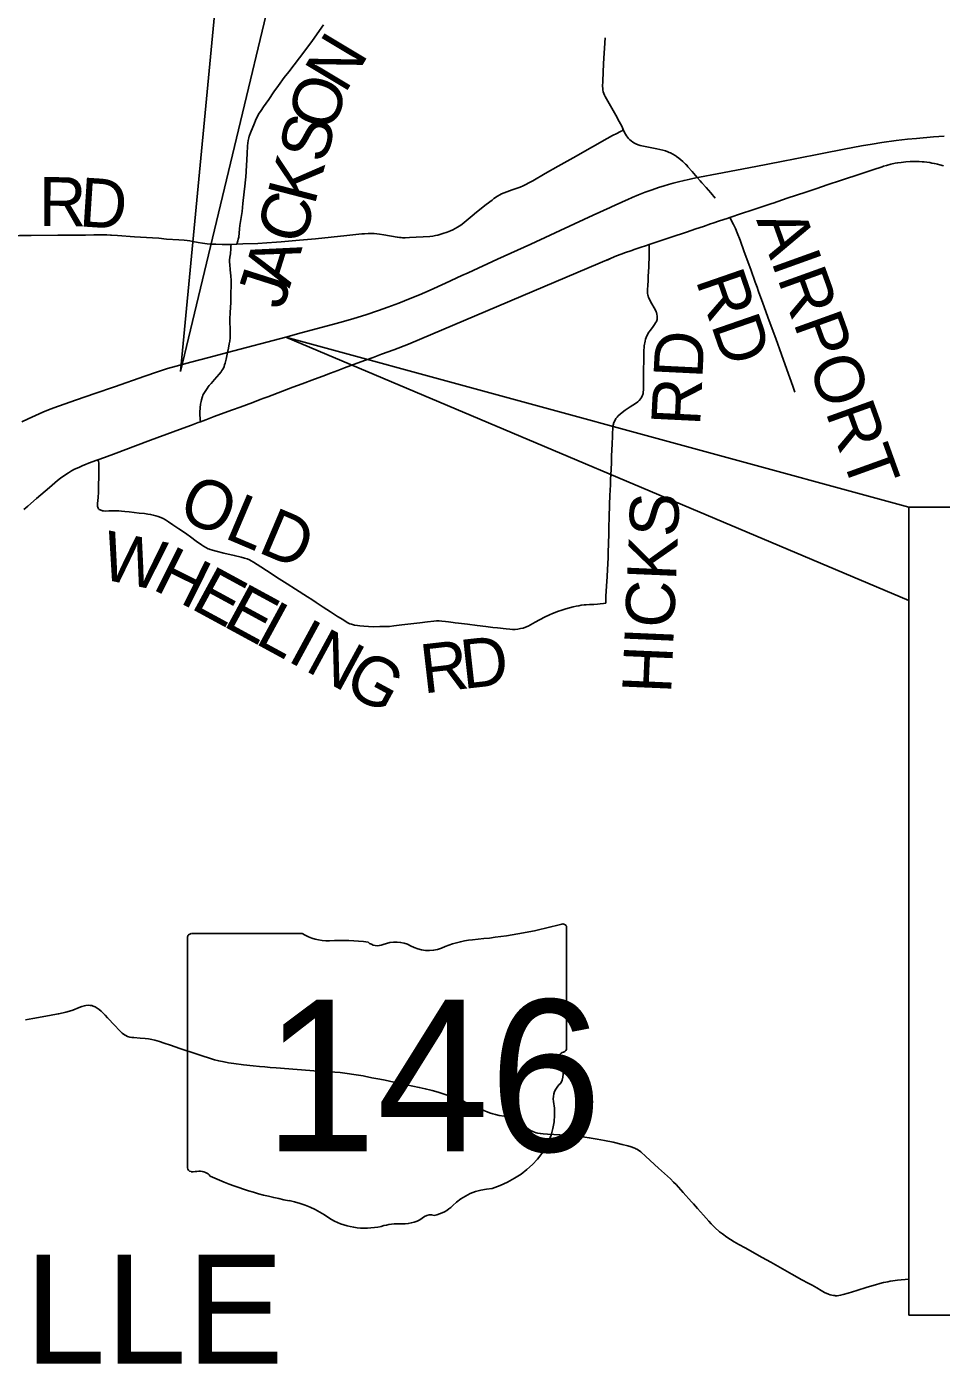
# Model space of a CAD drawing. Extents: x 1761803 to 2441803, y 509895 to 949895.
# Drawn here: x 2124353 to 2141149, y 790412 to 814988 of the extents above; entities that cross this region are included whole.
import ezdxf

# ---------------------------------------------------------------- set-up
doc = ezdxf.new("R2010")
doc.units = 0
for name, color, linetype in [('GM_X_County_Road', 7, 'Continuous'), ('GM_X_Minor_Lake', 7, 'Continuous'), ('GM_X_Minor_River', 7, 'Continuous'), ('GM_X_Minor_River_Text', 7, 'Continuous'), ('GM_X_State_Location', 7, 'Continuous'), ('GM_X_Township_Road', 7, 'Continuous')]:
    doc.layers.add(name, color=color, linetype=linetype)

msp = doc.modelspace()

# ---------------------------------------------------------------- linework, layer by layer
at = {"layer": 'GM_X_County_Road'}
for points in [[(2129165, 814161), (2129458, 814549), (2129600, 814737), (2129806, 815021)], [(2135308, 813102), (2135280, 813161), (2135235, 813247), (2135172, 813364), (2134976, 813705), (2134962, 813735), (2134951, 813765), (2134942, 813796), (2134935, 813828), (2134931, 813860), (2134930, 813892), (2134932, 813990), (2134948, 814312), (2134974, 814787)], [(2128212, 810995), (2128231, 811058), (2128237, 811085), (2128246, 811125), (2128259, 811278), (2128267, 811338), (2128307, 811596), (2128324, 811745), (2128367, 812116), (2128373, 812181), (2128377, 812229), (2128399, 812654), (2128407, 812801), (2128412, 812850), (2128420, 812898), (2128431, 812946), (2128441, 812977), (2128446, 812992), (2128463, 813038), (2128475, 813068), (2128524, 813190), (2128568, 813295), (2128589, 813340), (2128612, 813383), (2128656, 813452), (2128702, 813520), (2128797, 813653), (2128892, 813792), (2128977, 813911), (2129081, 814055), (2129165, 814161)], [(2132900, 811807), (2132934, 811833), (2132999, 811880), (2133039, 811905), (2133073, 811922), (2133119, 811941), (2133269, 811994), (2133414, 812045), (2133473, 812068), (2133517, 812090), (2133574, 812121), (2133645, 812161), (2133872, 812292), (2134116, 812427), (2134387, 812580), (2134743, 812782), (2135014, 812935), (2135114, 812989), (2135188, 813029), (2135247, 813057), (2135270, 813068), (2135286, 813080), (2135308, 813102)], [(2136151, 812681), (2136129, 812690), (2136083, 812707), (2136035, 812721), (2135923, 812746), (2135650, 812801), (2135618, 812809), (2135584, 812820), (2135539, 812839), (2135513, 812852), (2135485, 812870), (2135455, 812893), (2135432, 812913), (2135408, 812936), (2135387, 812961), (2135369, 812987), (2135351, 813016), (2135333, 813047), (2135308, 813102)], [(2136280, 812612), (2136261, 812624), (2136218, 812648), (2136174, 812671), (2136151, 812681)], [(2136474, 812444), (2136452, 812467), (2136405, 812513), (2136368, 812546), (2136329, 812577), (2136289, 812606), (2136280, 812612)], [(2136994, 811840), (2136916, 811936), (2136829, 812034), (2136749, 812125), (2136721, 812157), (2136668, 812219), (2136572, 812332), (2136497, 812419), (2136474, 812444)], [(2132380, 811386), (2132384, 811388), (2132388, 811391), (2132535, 811518), (2132611, 811581), (2132792, 811722), (2132900, 811807)], [(2128212, 810995), (2128321, 811000), (2128599, 811011), (2128763, 811020), (2128940, 811030), (2129024, 811037), (2129365, 811070), (2129659, 811095), (2130229, 811156), (2130506, 811184), (2130555, 811188), (2130621, 811191), (2130686, 811191), (2130735, 811189), (2130784, 811185), (2130833, 811179), (2130914, 811167), (2131158, 811127), (2131202, 811119), (2131227, 811117), (2131253, 811115), (2131302, 811114), (2131383, 811117), (2131759, 811140), (2131810, 811145), (2131858, 811154), (2131903, 811164), (2131997, 811192), (2132074, 811218), (2132135, 811241), (2132180, 811261), (2132224, 811282), (2132266, 811307), (2132323, 811344), (2132380, 811386)], [(2137767, 810205), (2137733, 810298), (2137649, 810529), (2137532, 810853), (2137453, 811068), (2137400, 811206), (2137369, 811282), (2137334, 811356), (2137269, 811488)], [(2123340, 810199), (2123493, 810385), (2123751, 810703), (2124047, 811054), (2124099, 811111), (2124113, 811122), (2124127, 811131), (2124143, 811138), (2124158, 811143), (2124173, 811147), (2124189, 811150), (2124221, 811153), (2124270, 811156), (2124434, 811156), (2124926, 811161), (2125171, 811164), (2125433, 811164), (2125586, 811166)], [(2125586, 811166), (2125630, 811166), (2125712, 811167), (2125826, 811165), (2125894, 811162)], [(2125894, 811162), (2125908, 811161), (2126022, 811154), (2126333, 811132), (2126660, 811111), (2126780, 811104), (2126921, 811091), (2127149, 811073), (2127247, 811067), (2127297, 811063), (2127351, 811056), (2127406, 811046), (2127502, 811028), (2127583, 811014), (2127664, 811004), (2127746, 810997), (2127828, 810994), (2127943, 810992), (2128105, 810991)], [(2127544, 807736), (2127540, 807773), (2127537, 807803), (2127532, 807855), (2127535, 807910), (2127540, 807989), (2127547, 808060), (2127555, 808106), (2127562, 808138), (2127572, 808178), (2127579, 808199), (2127589, 808226), (2127605, 808253), (2127628, 808289), (2127665, 808347), (2127686, 808378), (2127705, 808403), (2127738, 808440), (2127770, 808477), (2127804, 808514), (2127847, 808561), (2127890, 808611), (2127921, 808650), (2127939, 808677), (2127956, 808704), (2127970, 808730), (2127978, 808749), (2127988, 808780), (2127996, 808812), (2128013, 808887), (2128040, 809008), (2128057, 809084), (2128073, 809165), (2128081, 809214), (2128089, 809279), (2128092, 809361), (2128092, 809411), (2128086, 809592), (2128086, 809657), (2128088, 809706), (2128091, 809756), (2128093, 809822), (2128100, 809936), (2128102, 810055), (2128108, 810273), (2128107, 810331), (2128101, 810413), (2128091, 810527), (2128080, 810621), (2128077, 810665), (2128079, 810705), (2128085, 810756), (2128094, 810819), (2128103, 810915), (2128104, 810955), (2128105, 810991)], [(2128105, 810991), (2128212, 810995)], [(2134989, 804406), (2134989, 804459), (2134991, 804533), (2135002, 804718), (2135012, 804892), (2135020, 805023), (2135029, 805236), (2135034, 805384), (2135036, 805449), (2135039, 805548), (2135041, 805630), (2135042, 805695), (2135044, 805760), (2135046, 805842), (2135048, 805940), (2135052, 806054), (2135056, 806136), (2135058, 806218), (2135065, 806381), (2135068, 806480), (2135072, 806578), (2135075, 806676), (2135084, 806856), (2135090, 806987), (2135095, 807102), (2135106, 807331), (2135111, 807463), (2135114, 807544), (2135116, 807593), (2135120, 807642), (2135124, 807674), (2135128, 807690), (2135132, 807706), (2135143, 807736), (2135158, 807766), (2135175, 807793), (2135195, 807818), (2135217, 807842), (2135253, 807876), (2135291, 807906), (2135343, 807946), (2135383, 807974), (2135438, 808010), (2135534, 808073), (2135574, 808102), (2135595, 808120), (2135602, 808127), (2135631, 808163), (2135640, 808177), (2135648, 808191), (2135662, 808221), (2135667, 808237), (2135672, 808253), (2135677, 808285), (2135681, 808318), (2135683, 808367), (2135683, 808482), (2135683, 808564), (2135682, 808679), (2135685, 808875), (2135687, 808973), (2135687, 809022), (2135688, 809055), (2135690, 809095), (2135693, 809127), (2135698, 809157), (2135704, 809185), (2135709, 809216), (2135718, 809252), (2135729, 809284), (2135748, 809325), (2135778, 809378), (2135806, 809418), (2135856, 809482), (2135885, 809521), (2135903, 809549), (2135918, 809578), (2135924, 809594), (2135929, 809610), (2135932, 809626), (2135933, 809642), (2135934, 809659), (2135933, 809676), (2135927, 809708), (2135919, 809740), (2135913, 809756), (2135899, 809786), (2135876, 809829), (2135835, 809901), (2135811, 809943), (2135788, 809986), (2135775, 810016), (2135764, 810047), (2135761, 810062), (2135756, 810094), (2135755, 810127), (2135756, 810159), (2135761, 810241), (2135765, 810322), (2135769, 810403), (2135777, 810583), (2135784, 810794), (2135786, 810875), (2135787, 810990)], [(2137789, 810145), (2137767, 810205)], [(2138459, 808279), (2138424, 808386), (2138370, 808541), (2138313, 808695), (2138214, 808973), (2138108, 809266), (2137990, 809589), (2137873, 809913), (2137795, 810129), (2137789, 810145)], [(2125660, 807038), (2125670, 807007), (2125675, 806982), (2125678, 806936), (2125680, 806867), (2125679, 806737), (2125673, 806558), (2125671, 806509), (2125668, 806443), (2125662, 806346), (2125652, 806232), (2125651, 806199), (2125652, 806182), (2125656, 806166), (2125663, 806150), (2125673, 806137), (2125686, 806126), (2125700, 806117), (2125715, 806109), (2125731, 806104), (2125747, 806101), (2125764, 806099), (2125796, 806096), (2125862, 806097), (2125977, 806099), (2126042, 806099), (2126091, 806096), (2126156, 806089), (2126237, 806080), (2126416, 806060), (2126513, 806049), (2126578, 806041), (2126627, 806033), (2126675, 806022), (2126722, 806010), (2126769, 805995), (2126814, 805977), (2126858, 805956), (2126901, 805933), (2126957, 805899), (2127038, 805844), (2127147, 805771), (2127158, 805764)], [(2127158, 805764), (2127295, 805669), (2127362, 805621), (2127467, 805544), (2127561, 805478), (2127602, 805450), (2127644, 805425), (2127688, 805403), (2127711, 805394)], [(2127711, 805394), (2127719, 805391), (2127766, 805376), (2127829, 805359), (2127973, 805324), (2128165, 805280), (2128292, 805250), (2128355, 805233), (2128402, 805217), (2128447, 805199), (2128476, 805184), (2128518, 805159), (2128655, 805069), (2128861, 804935), (2128943, 804880), (2129039, 804818), (2129133, 804758), (2129287, 804662), (2129510, 804520), (2129590, 804470), (2129669, 804417), (2129797, 804333), (2129934, 804243), (2130062, 804162), (2130156, 804105), (2130240, 804052), (2130290, 804027), (2130317, 804018), (2130333, 804013)], [(2132099, 804060), (2132187, 804050), (2132219, 804046), (2132284, 804038), (2132446, 804018), (2132624, 803995), (2132786, 803975), (2132916, 803960), (2132997, 803951), (2133160, 803931), (2133225, 803924), (2133274, 803922), (2133324, 803923), (2133373, 803928), (2133421, 803937), (2133469, 803948), (2133516, 803964), (2133561, 803982), (2133605, 804004), (2133691, 804053), (2133864, 804145), (2133952, 804190), (2134011, 804217), (2134056, 804236), (2134103, 804252), (2134180, 804277), (2134257, 804302), (2134321, 804321), (2134391, 804339), (2134445, 804351), (2134491, 804358), (2134538, 804365), (2134593, 804373), (2134626, 804376), (2134690, 804379), (2134770, 804383), (2134835, 804387), (2134884, 804392), (2134947, 804399), (2134989, 804406)], [(2130333, 804013), (2130372, 804003), (2130425, 803995), (2130471, 803988), (2130544, 803980), (2130632, 803974), (2130719, 803971), (2130836, 803973), (2130934, 803974), (2131016, 803978), (2131098, 803986), (2131244, 804004), (2131570, 804041), (2131716, 804060), (2131830, 804073), (2131879, 804077), (2131927, 804077), (2131976, 804074), (2132041, 804068), (2132099, 804060), (2132099, 804060)]]:
    msp.add_lwpolyline(points, dxfattribs=at)
at = {"layer": 'GM_X_Minor_Lake'}
for points in [[(2124933, 796865), (2124941, 796867), (2125073, 796893), (2125138, 796912), (2125199, 796933), (2125316, 796980), (2125365, 797000), (2125412, 797013), (2125440, 797019), (2125481, 797022), (2125518, 797020), (2125546, 797015), (2125573, 797006), (2125610, 796990), (2125647, 796969), (2125682, 796945), (2125720, 796910), (2125768, 796865), (2125792, 796838), (2125836, 796789), (2125970, 796648), (2126053, 796562), (2126105, 796512), (2126132, 796491), (2126158, 796472), (2126172, 796464), (2126203, 796449), (2126244, 796437), (2126281, 796432), (2126320, 796428), (2126434, 796419), (2126527, 796412), (2126592, 796402), (2126650, 796391), (2126708, 796378), (2126789, 796357), (2126874, 796328), (2126994, 796287)], [(2124332, 796752), (2124462, 796776), (2124768, 796832), (2124933, 796865)], [(2126994, 796287), (2127163, 796228), (2127802, 796021), (2127881, 796001), (2127977, 795980), (2128058, 795966), (2128155, 795952), (2128334, 795929), (2128513, 795909), (2128627, 795897), (2128725, 795889), (2128822, 795881), (2128936, 795874), (2129703, 795814), (2130014, 795792), (2130112, 795784), (2130193, 795774), (2130404, 795744), (2130534, 795725), (2130557, 795720), (2130694, 795691), (2130839, 795663), (2130935, 795643), (2131095, 795609), (2131561, 795512), (2131673, 795488), (2131773, 795462)], [(2131773, 795462), (2131800, 795455), (2131911, 795423), (2132036, 795384), (2132160, 795342), (2132252, 795307), (2132385, 795253), (2132404, 795245), (2132539, 795186), (2132748, 795091), (2132809, 795065), (2132854, 795047), (2132916, 795027), (2132963, 795013), (2133027, 794999), (2133123, 794982), (2133196, 794973), (2133247, 794963), (2133284, 794951), (2133318, 794938), (2133348, 794921), (2133375, 794906), (2133413, 794877), (2133464, 794835), (2133539, 794771), (2133564, 794751), (2133604, 794724), (2133647, 794701), (2133677, 794689), (2133708, 794680), (2133739, 794672), (2133787, 794664), (2133836, 794659), (2133918, 794655), (2134032, 794650), (2134262, 794639), (2134360, 794631), (2134386, 794628), (2134441, 794621), (2134684, 794588), (2134830, 794563), (2134962, 794541), (2135121, 794506), (2135286, 794464), (2135391, 794439), (2135454, 794421), (2135501, 794406), (2135532, 794394), (2135542, 794388), (2135561, 794378), (2135588, 794359), (2135631, 794328), (2135723, 794245), (2135956, 794031), (2136064, 793932), (2136174, 793832), (2136232, 793775), (2136278, 793728), (2136410, 793584), (2136562, 793412), (2136596, 793376), (2136673, 793291), (2136782, 793169), (2136880, 793059), (2136925, 793011), (2136993, 792940), (2137078, 792864), (2137130, 792824), (2137209, 792766), (2137277, 792721), (2137347, 792679), (2137433, 792630), (2137547, 792566), (2137862, 792391), (2138019, 792302), (2138405, 792086), (2138590, 791982), (2138705, 791919), (2138776, 791879), (2138861, 791830), (2138946, 791781), (2139004, 791750), (2139048, 791729), (2139067, 791721), (2139078, 791716), (2139109, 791706), (2139140, 791698), (2139172, 791692), (2139196, 791690), (2139204, 791689), (2139237, 791689), (2139269, 791692), (2139301, 791697), (2139348, 791709), (2139442, 791738), (2139598, 791787), (2139786, 791844), (2139943, 791889), (2140022, 791911), (2140086, 791928), (2140133, 791939), (2140165, 791945), (2140213, 791953), (2140261, 791961), (2140343, 791971), (2140551, 791993)]]:
    msp.add_lwpolyline(points, dxfattribs=at)
at = {"layer": 'GM_X_Minor_River'}
msp.add_lwpolyline([(2124261, 807734), (2124378, 807792), (2124513, 807853), (2124648, 807911), (2124786, 807965), (2124939, 808022), (2125265, 808135), (2125605, 808254), (2125962, 808378), (2126519, 808573), (2126752, 808651), (2126940, 808711), (2127097, 808757), (2127366, 808831), (2127699, 808918), (2128040, 809008), (2129111, 809291), (2129396, 809368), (2129967, 809519), (2130173, 809575), (2130362, 809631), (2130581, 809701), (2130814, 809779), (2130984, 809839), (2131184, 809914), (2131398, 809998), (2131565, 810067), (2131760, 810152), (2132044, 810281), (2132342, 810418), (2132346, 810420), (2132462, 810472), (2132999, 810719), (2133610, 810999), (2134414, 811370), (2134758, 811526), (2135071, 811670), (2135182, 811722), (2135205, 811732), (2135296, 811774), (2135393, 811817), (2135474, 811853), (2135591, 811902), (2135714, 811950), (2135841, 811996), (2135959, 812036), (2136061, 812067), (2136142, 812091), (2136225, 812116), (2136324, 812142), (2136425, 812166), (2136536, 812192), (2136668, 812219), (2136709, 812227), (2137036, 812289), (2137746, 812424), (2138218, 812517), (2138463, 812565), (2138962, 812662), (2139364, 812739), (2139687, 812801), (2139881, 812834), (2140059, 812862), (2140319, 812897), (2140530, 812923), (2140694, 812939), (2141004, 812964), (2141204, 812980)], dxfattribs=at)
at = {"layer": 'GM_X_Minor_River_Text'}
for points in [[(2138060, 811752), (2138149, 811782), (2138320, 811839), (2138663, 811954), (2138865, 812020), (2139052, 812083), (2139317, 812171), (2139675, 812290), (2139893, 812364), (2140064, 812419), (2140089, 812426), (2140143, 812442), (2140222, 812463), (2140302, 812481), (2140350, 812490), (2140415, 812498), (2140496, 812506), (2140578, 812511), (2140660, 812513), (2140742, 812512), (2140797, 812509), (2140838, 812505), (2140887, 812500), (2140938, 812493), (2140977, 812486), (2141019, 812479), (2141058, 812471), (2141081, 812465), (2141121, 812455), (2141193, 812435)], [(2137269, 811488), (2137355, 811518), (2137388, 811529), (2137760, 811652), (2137853, 811684), (2137980, 811725), (2138040, 811745), (2138060, 811752)], [(2135016, 810704), (2135089, 810740), (2135182, 810781), (2135268, 810814), (2135349, 810842), (2135446, 810875), (2135527, 810903), (2135638, 810940), (2135720, 810968), (2135787, 810990), (2136003, 811061), (2136189, 811124), (2136469, 811219), (2136640, 811276), (2136780, 811323), (2136909, 811367)], [(2136909, 811367), (2136951, 811381), (2137076, 811423), (2137215, 811470), (2137269, 811488)], [(2128707, 808168), (2128779, 808196), (2129240, 808368), (2129409, 808431), (2129640, 808515), (2129793, 808574), (2129931, 808625), (2130069, 808677), (2130192, 808723), (2130423, 808809), (2130576, 808867), (2130715, 808918), (2130868, 808976), (2131097, 809059), (2131363, 809159), (2135084, 810738), (2135089, 810740)], [(2124298, 806122), (2124373, 806186), (2124534, 806326), (2124769, 806530), (2124919, 806657), (2124971, 806697), (2125037, 806744), (2125120, 806798), (2125176, 806832), (2125233, 806863), (2125307, 806898), (2125382, 806931), (2125431, 806950), (2125489, 806972), (2125642, 807031), (2125660, 807038), (2125781, 807081), (2125996, 807161), (2126350, 807291), (2126626, 807395), (2127041, 807549), (2127226, 807618), (2127380, 807675), (2127503, 807720), (2127544, 807736), (2127641, 807771), (2127795, 807829), (2127979, 807898), (2128133, 807954), (2128272, 808006), (2128503, 808091), (2128641, 808143), (2128707, 808168)]]:
    msp.add_lwpolyline(points, dxfattribs=at)
at = {"layer": 'GM_X_State_Location'}
for points in [[(2127176, 808660), (2128253, 819961), (2129889, 819961)], [(2129111, 809291), (2140551, 806169), (2140551, 804452)], [(2140551, 791334), (2169928, 791334), (2169928, 806169), (2140551, 806169)]]:
    msp.add_lwpolyline(points, close=True, dxfattribs=at)
at = {"layer": 'GM_X_Township_Road'}
for p, q in [((2127308, 798265), (2127308, 794039)), ((2129415, 798338), (2127376, 798338)), ((2134269, 796232), (2134269, 798443)), ((2134268, 796232), (2134269, 796232))]:
    msp.add_line(p, q, dxfattribs=at)
for centre, major_axis, start_param, end_param in [((2131789, 804100), (7382, 0), 4.814394, 5.042369), ((2134191, 798452), (77.5, 0), 6.141152, 7.989035), ((2127387, 798274), (80.6, 0), 1.712693, 3.28349), ((2129900, 798829), (782, 0), 4.042523, 4.731795), ((2130160, 795965), (2808, 0), 1.404758, 1.657858), ((2130797, 798296), (226, 0), 3.836095, 5.185415), ((2131128, 797808), (469, 0), 0.950623, 2.079405), ((2131734, 798478), (564, 0), 4.081561, 5.145723), ((2132731, 797047), (1485, 0), 1.699011, 2.107814), ((2134251, 796070), (120, 0), 1.883978, 3.671073), ((2133488, 795790), (720, 0), 5.934695, 6.695948), ((2134186, 796223), (82.9, 0), 5.05454, 6.418171), ((2134546, 795307), (524, 0), 2.387724, 3.262537), ((2132202, 795025), (1846, 0), 5.101752, 6.440018), ((2127388, 794030), (81.4, 0), 3.00124, 4.508301), ((2127401, 794462), (621, 0), 4.665946, 4.897461), ((2127528, 793795), (224, 0), 0.519207, 1.627899), ((2130354, 797592), (5331, 0), 4.195997, 4.488961), ((2132981, 792852), (1011, 0), 1.647645, 2.488434), ((2128765, 792140), (1668, 0), 0.823519, 1.323587), ((2131700, 793629), (597, 0), 4.937069, 5.64225), ((2130569, 793774), (1058, 0), 4.026481, 4.996735), ((2131257, 793457), (564, 0), 4.691044, 5.507374), ((2131768, 793048), (159, 0), 1.147584, 2.315152), ((2131180, 792313), (870, 0), 1.495662, 1.94098)]:
    msp.add_ellipse(centre, major_axis=major_axis, ratio=0.8, start_param=start_param, end_param=end_param, dxfattribs=at)

# ---------------------------------------------------------------- texts
at = {"layer": 'GM_X_County_Road'}
for s, height, rotation, p in [('N', 900, 59.0317, (2130196, 813742)), ('O', 900, 72.8066, (2129986, 813037)), ('S', 900, 75.5962, (2129838, 812460)), ('K', 900, 75.4364, (2129638, 811691)), ('R', 900, 359.7504, (2124576, 811328)), ('D', 900, 356.2811, (2125301, 811325)), ('C', 900, 73.8068, (2129424, 810954)), ('AIRPORT', 900, 289.8051, (2137747, 811444)), ('A', 900, 72.455, (2129179, 810177)), ('J', 900, 72.3045, (2129050, 809772)), ('RD', 900, 289.0759, (2136631, 810339)), ('RD', 900, 87.2056, (2136719, 807649)), ('OLD', 900, 337.0095, (2127096, 805977)), ('HICKS', 900, 87.5293, (2136187, 802736)), ('W', 900, 348.3195, (2125675, 804860)), ('H', 900, 333.5045, (2126638, 804669)), ('E', 900, 331.5096, (2127340, 804320)), ('E', 900, 331.4786, (2127931, 803999)), ('L', 900, 331.4824, (2128523, 803677)), ('I', 900, 331.4843, (2129114, 803356)), ('N', 900, 331.4806, (2129439, 803179)), ('R', 900, 6.6109, (2131638, 802744)), ('D', 900, 6.3076, (2132371, 802829)), ('G', 900, 331.4806, (2130135, 802801)), ('ZANESVILLE', 2000, 0, (2112870, 790440))]:
    msp.add_text(s, height=height, rotation=rotation, dxfattribs=at).set_placement(p)
at = {"layer": 'GM_X_Township_Road'}
msp.add_text('146', height=2784.4, dxfattribs=at).set_placement((2128708, 794337))

doc.saveas('drawing.dxf')
